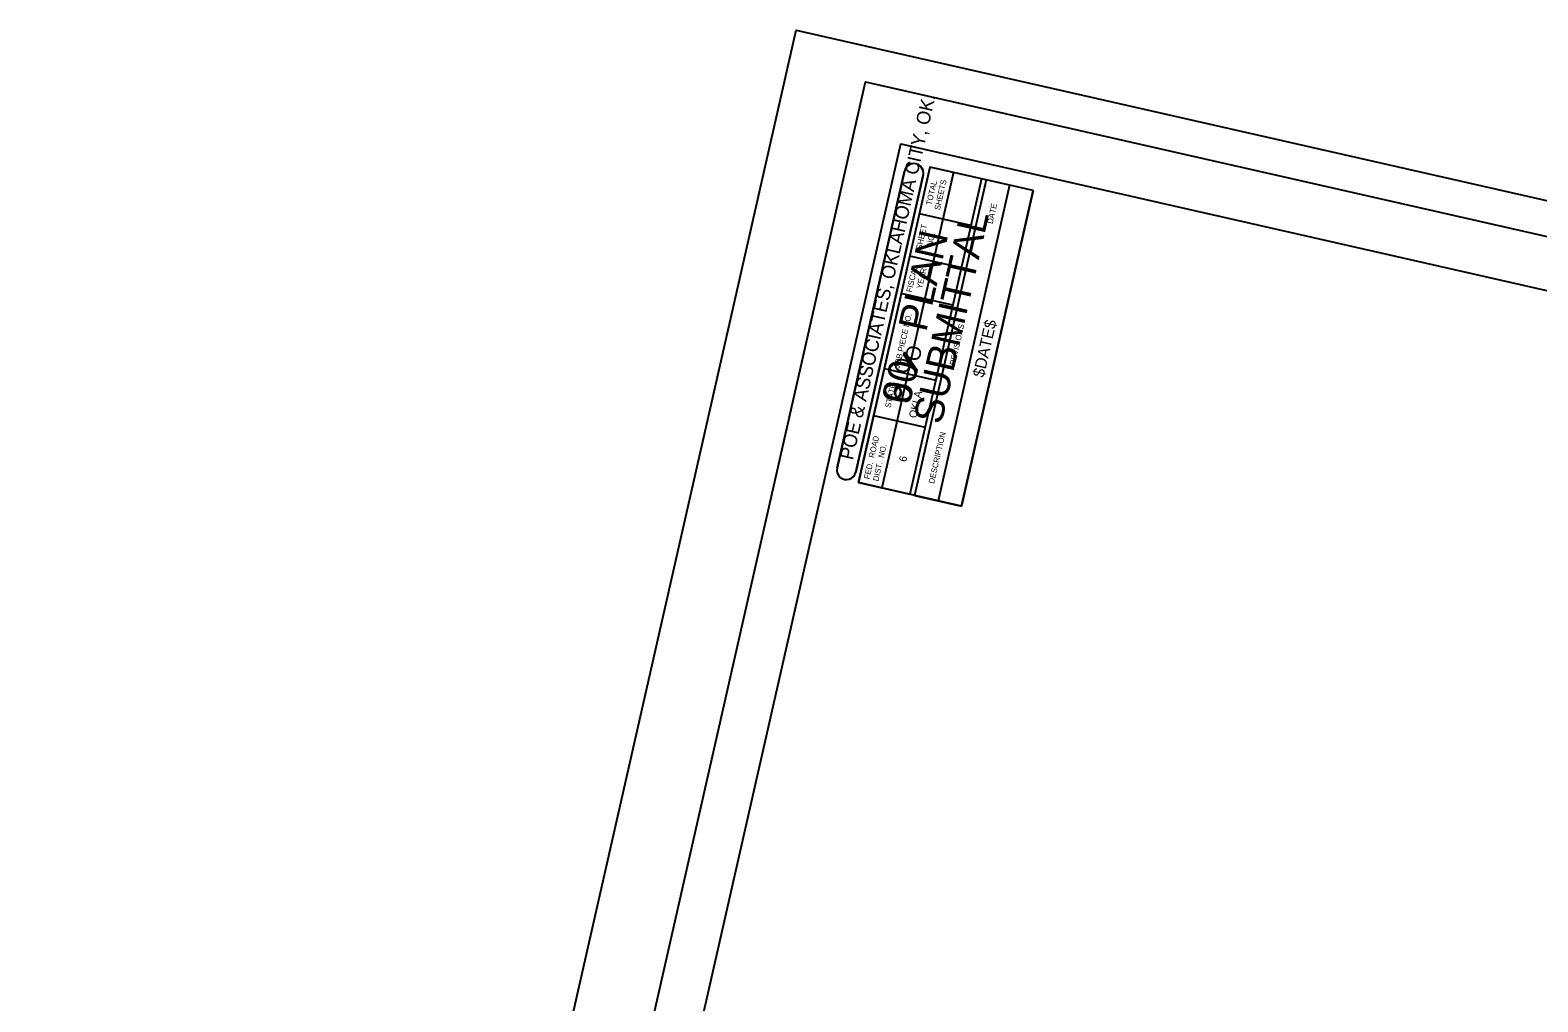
# Model space of a CAD drawing. Extents: x 2149833 to 2151401, y 143015 to 145036.
# Drawn here: x 2149833 to 2150617, y 144531 to 145036 of the extents above; entities that cross this region are included whole.
import ezdxf

# ---------------------------------------------------------------- set-up
doc = ezdxf.new("R2010")
doc.units = 0
for name, color, linetype in [('SHT_Date_Stamp', 7, 'Continuous'), ('SHT_Plot_Shape_Full', 7, 'Continuous'), ('SHT_Plot_Shape_Half', 7, 'Continuous'), ('SHT_Sheet_Border', 7, 'Continuous'), ('SHT_Stamp_60_Submit', 7, 'Continuous'), ('SHT_Stamp_90_Submit', 7, 'Continuous'), ('SHT_Stamp_Rev_Block', 7, 'Continuous')]:
    doc.layers.add(name, color=color, linetype=linetype)

msp = doc.modelspace()

# ---------------------------------------------------------------- linework, layer by layer
at = {"layer": 'SHT_Plot_Shape_Full'}
msp.add_lwpolyline([(2149832.8, 143280.53), (2150231.21, 145035.88), (2151401.45, 144770.27), (2151003.04, 143014.92)], close=True, dxfattribs=at)
at = {"layer": 'SHT_Plot_Shape_Half'}
msp.add_lwpolyline([(2149891.15, 143351.24), (2150267.43, 145009.07), (2151340.14, 144765.6), (2150963.87, 143107.77)], close=True, dxfattribs=at)
at = {"layer": 'SHT_Sheet_Border'}
msp.add_lwpolyline([(2151309.68, 144744.32), (2150961.07, 143208.38), (2149937.11, 143440.79), (2150285.72, 144976.72)], close=True, dxfattribs=at)
at = {"layer": 'SHT_Stamp_60_Submit'}
for p, q in [((2150252.61, 144808.25), (2150287.65, 144962.61)), ((2150262.36, 144806.03), (2150297.4, 144960.4)), ((2150263.69, 144800.61), (2150300.94, 144964.72)), ((2150354.54, 144952.56), (2150300.94, 144964.72)), ((2150317.29, 144788.44), (2150354.54, 144952.56)), ((2150287.25, 144866.97), (2150287.59, 144868.46)), ((2150293.94, 144857.48), (2150287.25, 144866.97)), ((2150294.14, 144858.35), (2150287.45, 144867.84)), ((2150294.19, 144858.59), (2150287.5, 144868.08)), ((2150294.28, 144858.97), (2150287.59, 144868.46)), ((2150293.94, 144857.48), (2150294.28, 144858.97)), ((2150317.29, 144788.44), (2150263.69, 144800.61))]:
    msp.add_line(p, q, dxfattribs=at)
for centre, start, end in [((2150292.51, 144961.52), 347.21228, 167.21706), ((2150257.47, 144807.15), 167.2075, 347.21228)]:
    msp.add_arc(centre, 5, start, end, dxfattribs=at)
at = {"layer": 'SHT_Stamp_90_Submit'}
for p, q in [((2150252.61, 144808.25), (2150287.65, 144962.61)), ((2150262.36, 144806.03), (2150297.4, 144960.4)), ((2150263.69, 144800.61), (2150300.94, 144964.72)), ((2150354.54, 144952.56), (2150300.94, 144964.72)), ((2150317.29, 144788.44), (2150354.54, 144952.56)), ((2150287.25, 144866.97), (2150287.59, 144868.46)), ((2150293.94, 144857.48), (2150287.25, 144866.97)), ((2150294.14, 144858.35), (2150287.45, 144867.84)), ((2150294.19, 144858.59), (2150287.5, 144868.08)), ((2150294.28, 144858.97), (2150287.59, 144868.46)), ((2150293.94, 144857.48), (2150294.28, 144858.97)), ((2150317.29, 144788.44), (2150263.69, 144800.61))]:
    msp.add_line(p, q, dxfattribs=at)
for centre, start, end in [((2150292.51, 144961.52), 347.21228, 167.21706), ((2150257.47, 144807.15), 167.2075, 347.21228)]:
    msp.add_arc(centre, 5, start, end, dxfattribs=at)
at = {"layer": 'SHT_Stamp_Rev_Block'}
for p, q in [((2150287.61, 144962.62), (2150252.57, 144808.27)), ((2150297.36, 144960.41), (2150262.32, 144806.05)), ((2150300.9, 144964.73), (2150263.65, 144800.61)), ((2150313.09, 144961.97), (2150275.84, 144797.85)), ((2150327.72, 144958.65), (2150300.9, 144964.73)), ((2150327.72, 144958.65), (2150290.47, 144794.53)), ((2150330.16, 144958.09), (2150292.91, 144793.97)), ((2150342.35, 144955.32), (2150305.1, 144791.21)), ((2150354.54, 144952.56), (2150317.29, 144788.44)), ((2150354.54, 144952.56), (2150330.16, 144958.09)), ((2150322.19, 144934.27), (2150295.37, 144940.35)), ((2150317.21, 144912.32), (2150290.39, 144918.41)), ((2150312.78, 144892.82), (2150285.96, 144898.91)), ((2150277.11, 144859.9), (2150303.93, 144853.81)), ((2150271.57, 144835.52), (2150298.39, 144829.43)), ((2150263.65, 144800.61), (2150290.47, 144794.53)), ((2150292.91, 144793.97), (2150317.29, 144788.44))]:
    msp.add_line(p, q, dxfattribs=at)
for centre, start, end in [((2150292.48, 144961.52), 347.21228, 167.21228), ((2150257.47, 144807.15), 167.21228, 347.21228)]:
    msp.add_arc(centre, 5, start, end, dxfattribs=at)

# ---------------------------------------------------------------- texts
at = {"layer": 'SHT_Date_Stamp'}
msp.add_text('$DATE$', height=6, rotation=77.21228, dxfattribs=at).set_placement((2150328.89, 144854.96))
at = {"layer": 'SHT_Stamp_60_Submit'}
for s, height, p in [('POE & ASSOCIATES, OKLAHOMA CITY, OK.', 7, (2150260.78, 144812.03)), ('SUBMITTAL', 15, (2150306.78, 144830.36)), ('60   PLAN', 15, (2150290.27, 144840.47)), ('O', 7.65, (2150289.42, 144856.74)), ('O', 7.65, (2150295.22, 144863.21))]:
    msp.add_text(s, height=height, rotation=77.21228, dxfattribs=at).set_placement(p)
at = {"layer": 'SHT_Stamp_90_Submit'}
for s, height, p in [('POE & ASSOCIATES, OKLAHOMA CITY, OK.', 7, (2150260.78, 144812.03)), ('SUBMITTAL', 15, (2150306.78, 144830.36)), ('90   PLAN', 15, (2150290.27, 144840.47)), ('O', 7.65, (2150289.42, 144856.74)), ('O', 7.65, (2150295.22, 144863.21))]:
    msp.add_text(s, height=height, rotation=77.21228, dxfattribs=at).set_placement(p)
at = {"layer": 'SHT_Stamp_Rev_Block'}
for s, height, p in [('POE & ASSOCIATES, OKLAHOMA CITY, OK.', 7, (2150260.73, 144812.05)), ('TOTAL', 3, (2150301.73, 144944.67)), ('SHEETS', 3, (2150306.06, 144942.09)), ('DATE', 3, (2150333.49, 144934.96)), ('SHEET', 3, (2150296.48, 144921.53)), ('NO.', 3, (2150302, 144923.28)), ('FISCAL', 3, (2150291.45, 144899.35)), ('YEAR', 3, (2150296.77, 144901.16)), ('JOB PIECE NO.', 3, (2150285.02, 144859.73)), ('REVISIONS', 3, (2150313.98, 144861.39)), ('STATE', 3, (2150280.38, 144839.28)), ('OKLA.', 4, (2150293.76, 144833.89)), ('DESCRIPTION', 3, (2150303.05, 144799.86)), ('FED.  ROAD', 3, (2150269.39, 144802.17)), ('DIST.  NO.', 3, (2150274.06, 144801.11)), ('6', 4, (2150288.59, 144811.11))]:
    msp.add_text(s, height=height, rotation=77.21228, dxfattribs=at).set_placement(p)

doc.saveas('drawing.dxf')
